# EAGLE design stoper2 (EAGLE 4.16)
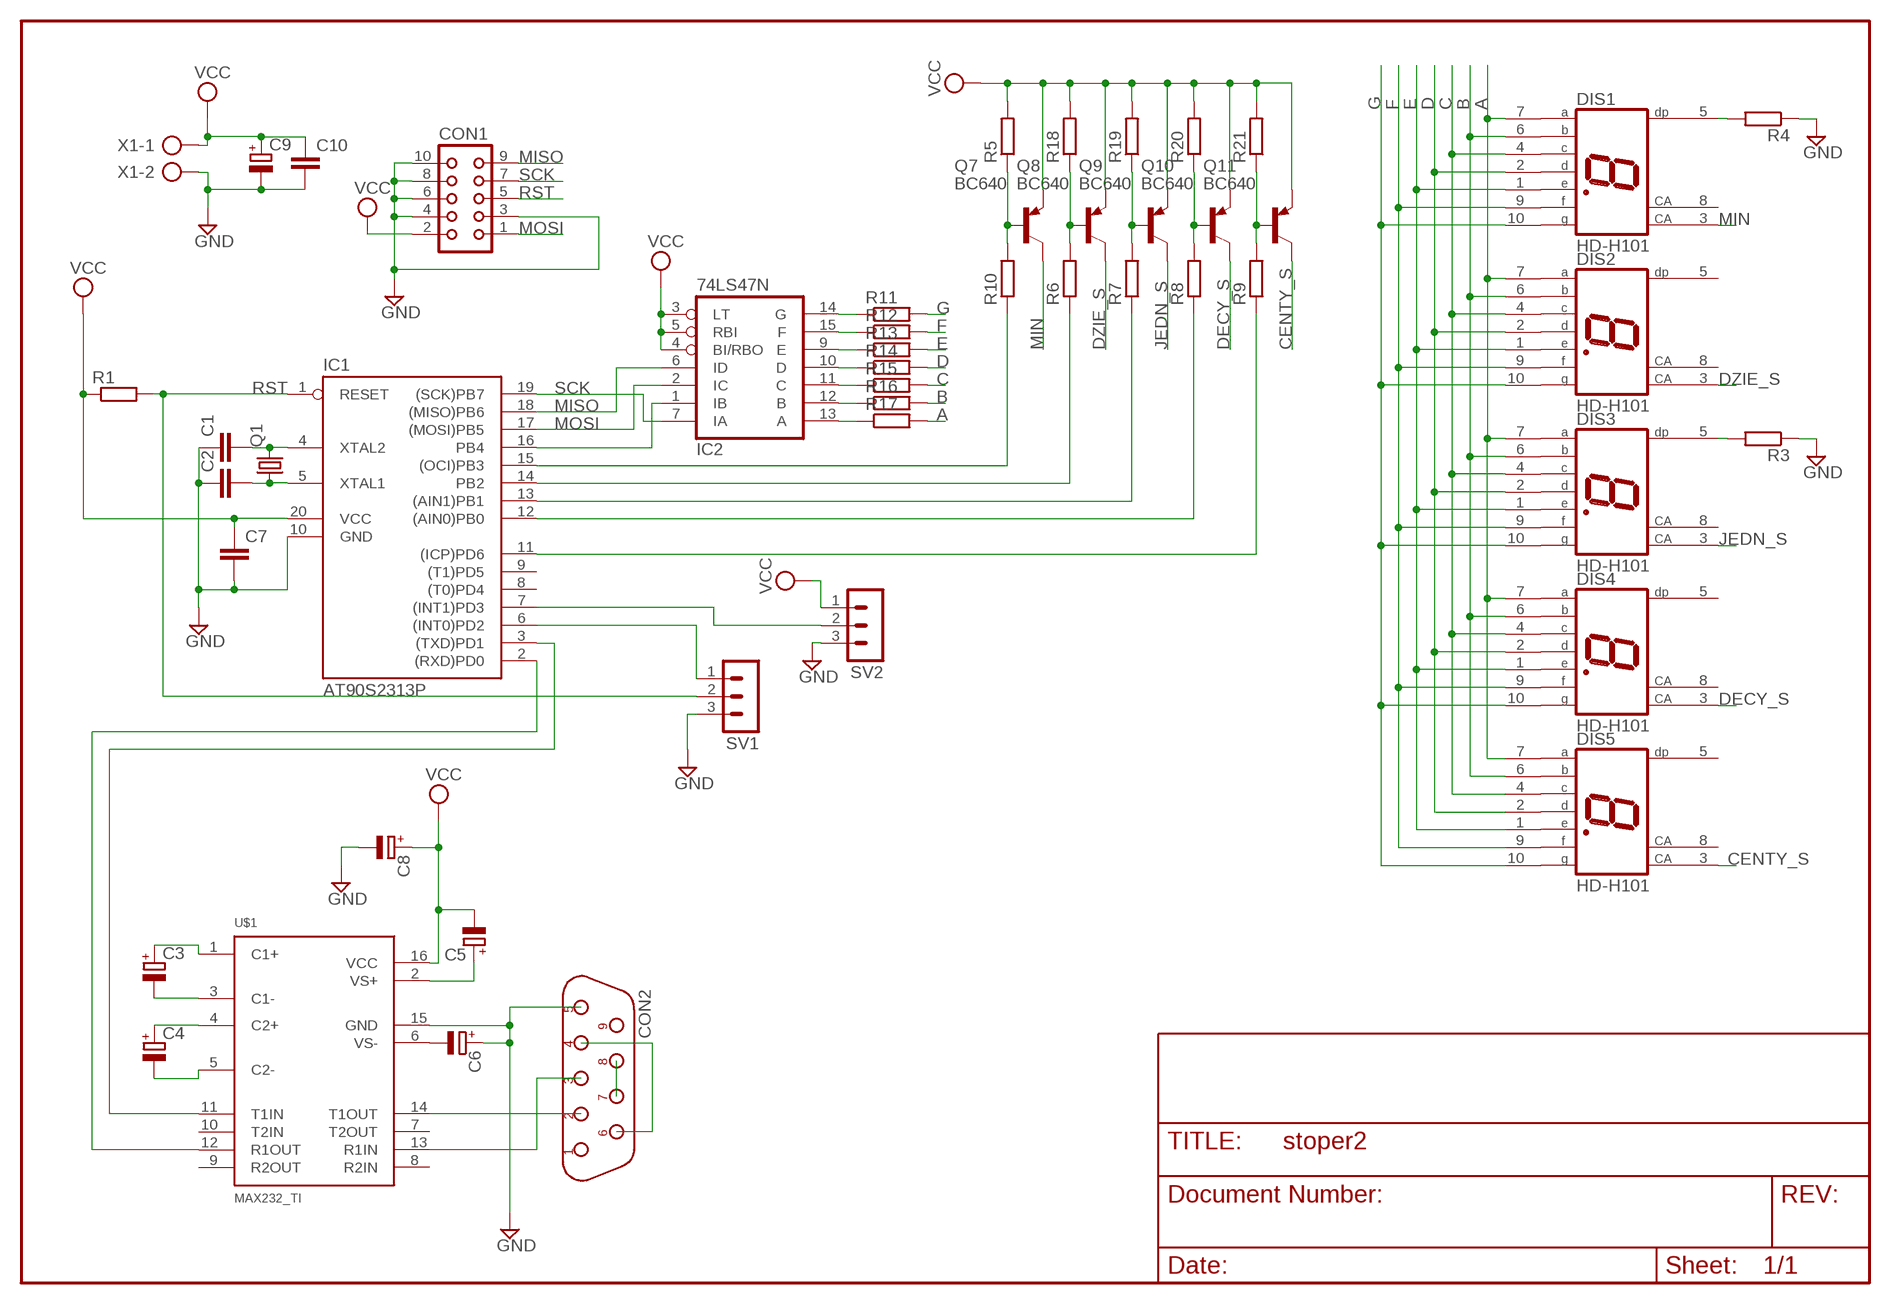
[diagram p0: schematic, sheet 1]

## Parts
C1  C5/2.5  [C5B2.5]
C2  C5/2.5  [C5B2.5]
C3  CPOL-EUE2.5-5  [E2,5-5]
C4  CPOL-EUE2.5-5  [E2,5-5]
C5  CPOL-EUE2.5-5  [E2,5-5]
C6  CPOL-EUE2.5-5  [E2,5-5]
C7  C5/2.5  [C5B2.5]
C8  CPOL-EUE2.5-5  [E2,5-5]
C9  CPOL-EUE2.5-5  [E2,5-5]
C10  C5/2.5  [C5B2.5]
CON1  CON10  [CON10]
CON2  DB9F/90  [D-09F/90]
DIS1  HD-H101  [HDSP-M]
DIS2  HD-H101  [HDSP-M]
DIS3  HD-H101  [HDSP-M]
DIS4  HD-H101  [HDSP-M]
DIS5  HD-H101  [HDSP-M]
IC1  AT90S2313P  [DIL20]
IC2  74LS47N  [DIL16]
Q1  CRYSTALHC49S  [HC49/S]
Q7  BC640  [TO92-BCE]
Q8  BC640  [TO92-BCE]
Q9  BC640  [TO92-BCE]
Q10  BC640  [TO92-BCE]
Q11  BC640  [TO92-BCE]
R1  R-EU_0204/7  [0204/7]
R3  R-EU_0204/5  [0204/5]
R4  R-EU_0204/5  [0204/5]
R5  R-EU_0204/5  [0204/5]
R6  R-EU_0204/5  [0204/5]
R7  R-EU_0204/5  [0204/5]
R8  R-EU_0204/5  [0204/5]
R9  R-EU_0204/5  [0204/5]
R10  R-EU_0204/5  [0204/5]
R11  R-EU_0204/7  [0204/7]
R12  R-EU_0204/7  [0204/7]
R13  R-EU_0204/7  [0204/7]
R14  R-EU_0204/7  [0204/7]
R15  R-EU_0204/7  [0204/7]
R16  R-EU_0204/7  [0204/7]
R17  R-EU_0204/7  [0204/7]
R18  R-EU_0204/5  [0204/5]
R19  R-EU_0204/5  [0204/5]
R20  R-EU_0204/5  [0204/5]
R21  R-EU_0204/5  [0204/5]
SV1  MA03-1  [MA03-1]
SV2  MA03-1  [MA03-1]
U$1  MAX232_TI  [DIL16]
X1  AK500/2  [AK500/2]

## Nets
A: DIS1.7(A) DIS2.7(A) DIS3.7(A) DIS4.7(A) DIS5.7(A) R17.2
B: DIS1.6(B) DIS2.6(B) DIS3.6(B) DIS4.6(B) DIS5.6(B) R16.2
C: DIS1.4(C) DIS2.4(C) DIS3.4(C) DIS4.4(C) DIS5.4(C) R15.2
CENTY_S: DIS5.3(CA) Q11.C
D: DIS1.2(D) DIS2.2(D) DIS3.2(D) DIS4.2(D) DIS5.2(D) R14.2
DECY_S: DIS4.3(CA) Q10.C
DZIE_S: DIS2.3(CA) Q8.C
E: DIS1.1(E) DIS2.1(E) DIS3.1(E) DIS4.1(E) DIS5.1(E) R13.2
F: DIS1.9(F) DIS2.9(F) DIS3.9(F) DIS4.9(F) DIS5.9(F) R12.2
G: DIS1.10(G) DIS2.10(G) DIS3.10(G) DIS4.10(G) DIS5.10(G) R11.2
GND: C1.1 C2.1 C6.+ C7.2 C8.- C9.- C10.2 CON1.3 CON1.4 CON1.6 CON1.8 CON1.10 CON2.5 IC1.10(GND) R3.1 R4.1 SV1.3 SV2.3 U$1.15(GND) X1.2
JEDN_S: DIS3.3(CA) Q9.C
MIN: DIS1.3(CA) Q7.C
MISO: CON1.9 IC1.18((MISO)PB6) IC2.6(ID)
MOSI: CON1.1 IC1.17((MOSI)PB5) IC2.2(IC)
N$1: C2.2 IC1.5(XTAL1) Q1.1
N$2: C1.2 IC1.4(XTAL2) Q1.2
N$3: DIS1.5(DP) R4.2
N$4: DIS3.5(DP) R3.2
N$5: C3.- U$1.3(C1-)
N$6: C3.+ U$1.1(C1+)
N$7: C4.+ U$1.4(C2+)
N$8: C4.- U$1.5(C2-)
N$9: C5.+ U$1.2(VS+)
N$10: C6.- U$1.6(VS-)
N$11: CON2.2 U$1.14(T1OUT)
N$12: CON2.3 U$1.13(R1IN)
N$13: CON2.7 CON2.8
N$14: CON2.4 CON2.6
N$15: IC1.3((TXD)PD1) U$1.11(T1IN)
N$16: IC1.2((RXD)PD0) U$1.12(R1OUT)
N$17: IC1.11((ICP)PD6) R9.1
N$18: Q7.B R5.1 R10.2
N$19: IC1.15((OCI)PB3) R10.1
N$20: IC1.7((INT1)PD3) SV2.2
N$21: Q8.B R6.2 R18.1
N$22: Q9.B R7.2 R19.1
N$23: Q10.B R8.2 R20.1
N$24: Q11.B R9.2 R21.1
N$25: IC1.6((INT0)PD2) SV1.1
N$31: IC2.14(G) R11.1
N$32: IC2.15(F) R12.1
N$33: IC2.9(E) R13.1
N$34: IC2.10(D) R14.1
N$35: IC2.11(C) R15.1
N$36: IC2.12(B) R16.1
N$37: IC2.13(A) R17.1
N$38: IC1.16(PB4) IC2.1(IB)
N$39: IC1.14(PB2) R6.1
N$40: IC1.13((AIN1)PB1) R7.1
N$41: IC1.12((AIN0)PB0) R8.1
RST: CON1.5 IC1.1(RESET) R1.2 SV1.2
SCK: CON1.7 IC1.19((SCK)PB7) IC2.7(IA)
VCC: C5.- C7.1 C8.+ C9.+ C10.1 CON1.2 IC1.20(VCC) IC2.3(LT) IC2.4(BI/RBO) IC2.5(RBI) Q7.E Q8.E Q9.E Q10.E Q11.E R1.1 R5.2 R18.2 R19.2 R20.2 R21.2 SV2.1 U$1.16(VCC) X1.1
Unconnected: CON2.1 CON2.9 DIS1.8(CA) DIS2.5(DP) DIS2.8(CA) DIS3.8(CA) DIS4.5(DP) DIS4.8(CA) DIS5.5(DP) DIS5.8(CA) IC1.8((T0)PD4) IC1.9((T1)PD5) U$1.7(T2OUT) U$1.8(R2IN) U$1.9(R2OUT) U$1.10(T2IN)

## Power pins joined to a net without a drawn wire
GND: IC2.8(GND)
VCC: IC2.16(VCC)

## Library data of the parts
C1 C2 C7 C10 = capacitor-wima:C: CAPACITOR
C3-C6 C8 C9 = rcl:CPOL-EU: POLARIZED CAPACITOR, European symbol
CON1 = con-harting:CON10: CONNECTOR
CON2 = connect:DB9F/90
DIS1-DIS5 = display-hp:HD-H101: LED DISPLAY 1-character 7 segment, decimal point right
IC1 = atmel:AT90S2313: MICROCONTROLLER 2 Kbytes FLASH 128 bytes SRAM 128 bytes EEPROM UART
IC2 = 74xx-eu:74*47: BCD to seven segment DECODER/DRIVER Source: http://www.ee.washington.edu/stores/DataSheets/74ls/74ls47.pdf
Q1 = crystal:CRYSTAL: CRYSTAL
Q7-Q11 = transistor-pnp:BC640*: PNP Transistror
R1 R3-R21 = rcl:R-EU_: RESISTOR, European symbol
SV1 SV2 = con-lstb:MA03-1: PIN HEADER
U$1 = max232ti:MAX232_TI: MAX232, Texas Instruments Version
X1 = con-ptr500:AK500/2: CONNECTOR

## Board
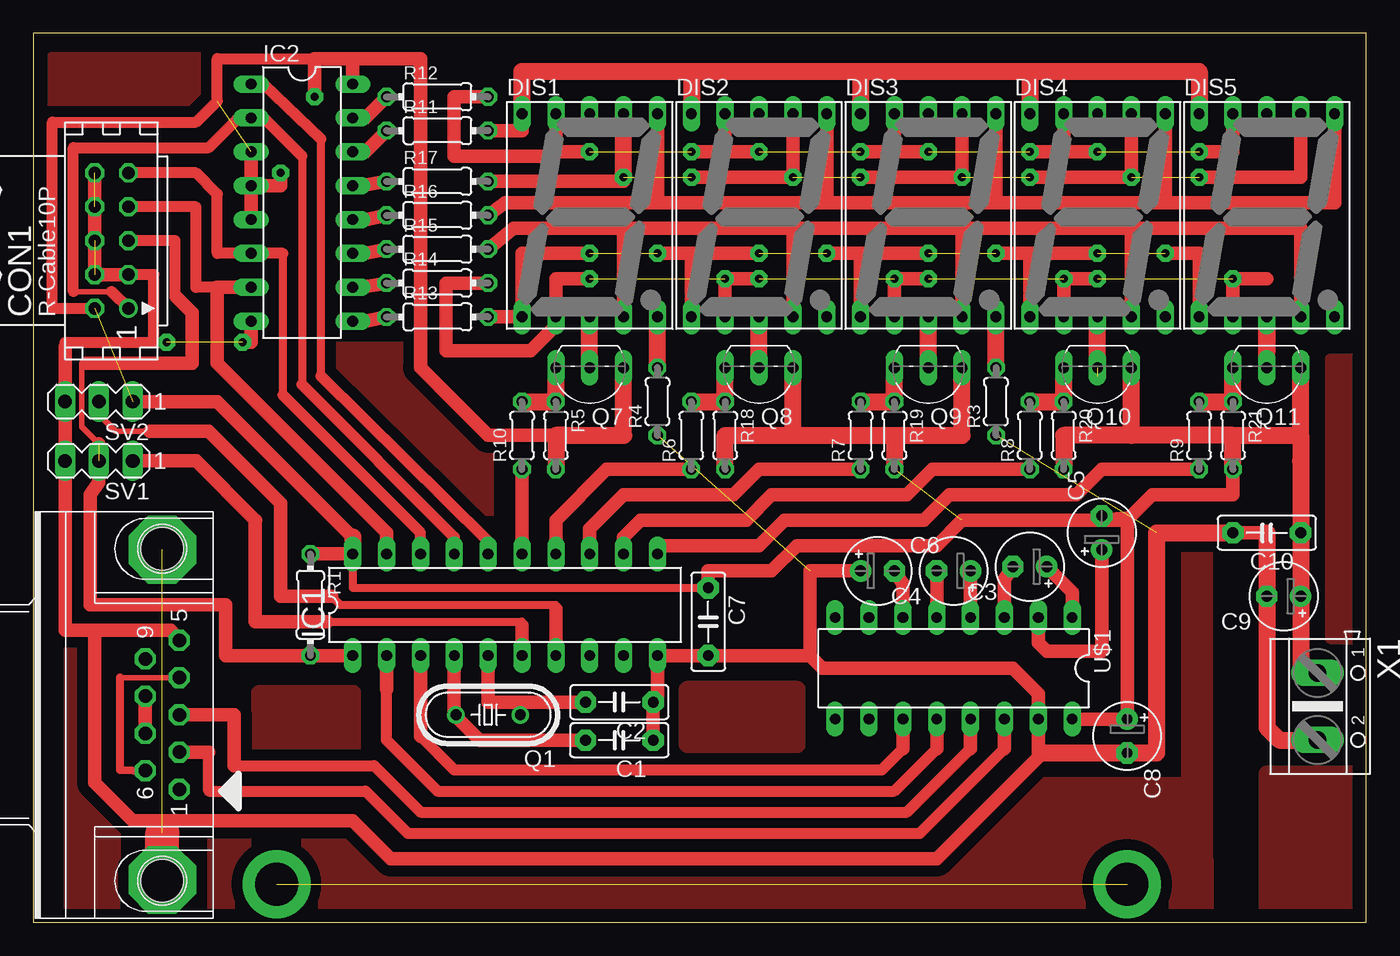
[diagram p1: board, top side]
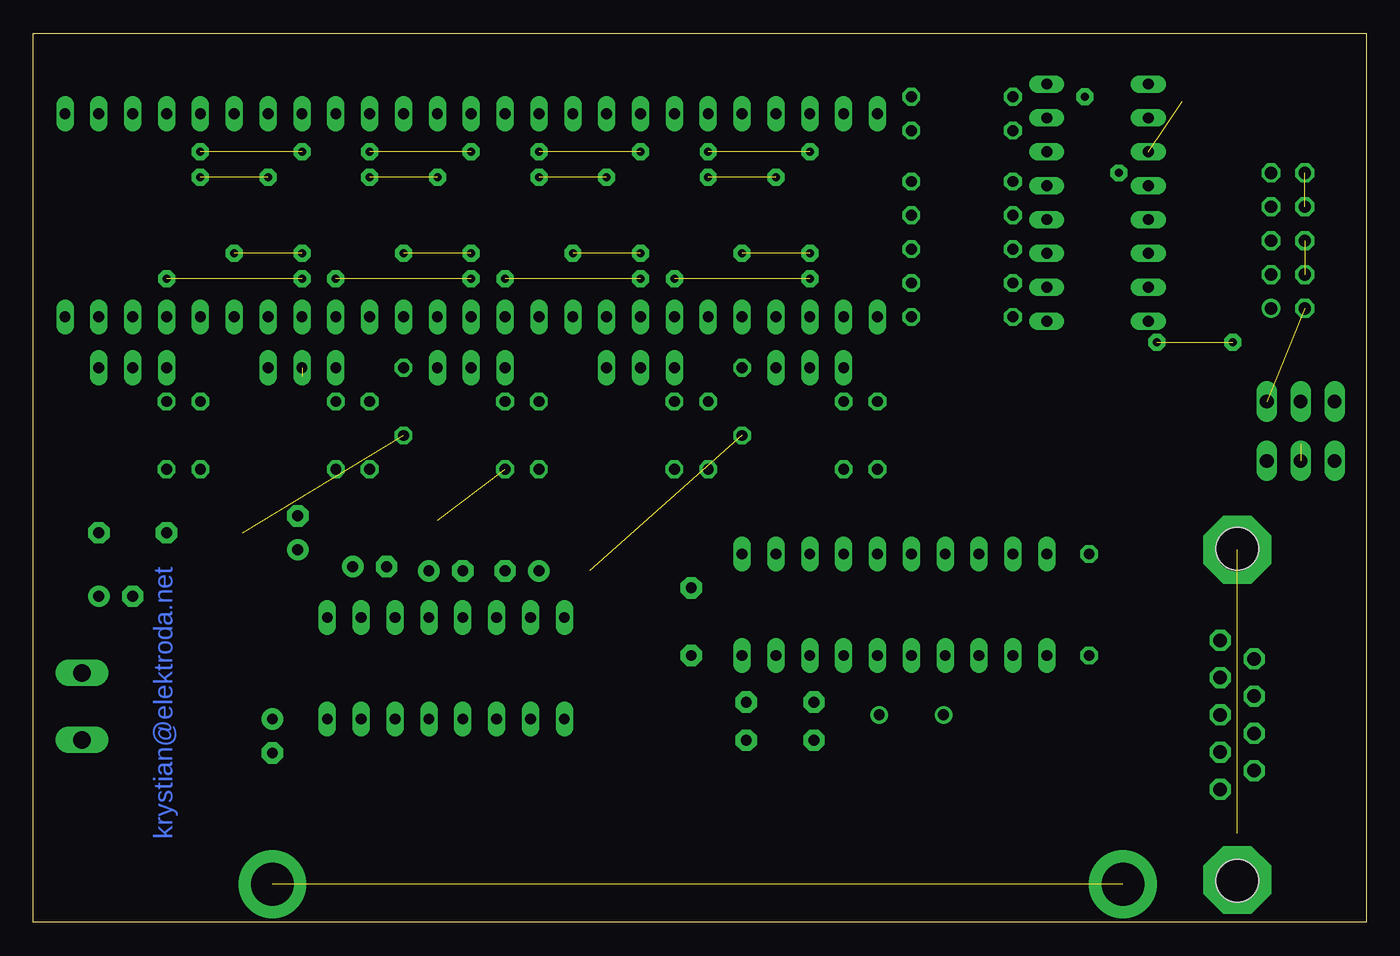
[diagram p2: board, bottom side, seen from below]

Size 100 x 66.67 mm. Coordinates in mm from the lower left corner, seen from the top.
Outline: 0,0 100,0 100,66.67 0,66.67 0,0
Copper layers (1*16): Top 0.035mm / dielectric 1.5mm / Bottom 0.035mm
Design rules "default": minimum track width 10mil, minimum drill 24mil, track to track 8mil, track to pad 8mil, pad to pad 8mil, via to via 8mil, smd to smd 8mil, copper to edge 40mil, drill to drill 8mil, minimum pad ring 10mil, minimum via ring 8mil, stop-mask expansion 4mil, vias tented up to drill 0mil, thermal gap 10mil

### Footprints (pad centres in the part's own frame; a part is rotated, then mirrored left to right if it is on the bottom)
C5B2.5 = drill 0.813 pad 1.6 octagon: 1 -2.54,0; 2 2.54,0
E2,5-5 = drill 0.813 pad 1.6 round: + -1.27,0 | drill 0.813 pad 1.6 octagon: - 1.27,0
CON10 = drill 0.914 round: 1 -5.08,-1.27 | drill 0.914 octagon: 2 -5.08,1.27; 3 -2.54,-1.27; 4 -2.54,1.27; 5 0,-1.27; 6 0,1.27; 7 2.54,-1.27; 8 2.54,1.27; 9 5.08,-1.27; 10 5.08,1.27
D-09F/90 = drill 1.016 pad 1.575 octagon: 1 -5.588,-1.27; 2 -2.794,-1.27; 3 0,-1.27; 4 2.794,-1.27; 5 5.588,-1.27; 6 -4.191,1.27; 7 -1.397,1.27; 8 1.397,1.27; 9 4.191,1.27 | hole 3.2: 12.446,0; -12.446,0
HDSP-M = drill 0.813 long: 1 -5.08,-7.62; 2 -2.54,-7.62; 3 0,-7.62; 4 2.54,-7.62; 5 5.08,-7.62; 6 5.08,7.62; 7 2.54,7.62; 8 0,7.62; 9 -2.54,7.62; 10 -5.08,7.62
DIL20 = drill 0.813 long: 1 -11.43,-3.81; 2 -8.89,-3.81; 3 -6.35,-3.81; 4 -3.81,-3.81; 5 -1.27,-3.81; 6 1.27,-3.81; 7 3.81,-3.81; 8 6.35,-3.81; 9 8.89,-3.81; 10 11.43,-3.81; 11 11.43,3.81; 12 8.89,3.81; 13 6.35,3.81; 14 3.81,3.81; 15 1.27,3.81; 16 -1.27,3.81; 17 -3.81,3.81; 18 -6.35,3.81; 19 -8.89,3.81; 20 -11.43,3.81
DIL16 = drill 0.813 long: 1 -8.89,-3.81; 2 -6.35,-3.81; 3 -3.81,-3.81; 4 -1.27,-3.81; 5 1.27,-3.81; 6 3.81,-3.81; 7 6.35,-3.81; 8 8.89,-3.81; 9 8.89,3.81; 10 6.35,3.81; 11 3.81,3.81; 12 1.27,3.81; 13 -1.27,3.81; 14 -3.81,3.81; 15 -6.35,3.81; 16 -8.89,3.81
HC49/S = drill 0.813 round: 1 -2.413,0; 2 2.413,0
TO92-BCE = drill 0.813 long: B 2.54,0; C 0,0; E -2.54,0
0204/7 = drill 0.813 octagon: 1 -3.81,0; 2 3.81,0
0204/5 = drill 0.813 octagon: 1 -2.54,0; 2 2.54,0
MA03-1 = drill 1.016 long: 1 -2.54,0; 2 0,0; 3 2.54,0
AK500/2 = drill 1.321 long: 1 -2.515,0; 2 2.515,0

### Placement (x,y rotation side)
C1  43.97,13.65 180 top
C2  43.97,16.51 180 top
C3  74.77,26.66 180 top
C4  69.05,26.35 180 top
C5  80.16,29.2 90 top
C6  63.34,26.35 0 top
C7  50.63,22.54 270 top
C8  82.07,13.97 270 top
C9  93.81,24.44 180 top
C10  92.55,29.2 180 top
CON1  5.87,51.11 90 top
CON2  9.68,15.55 90 top
DIS1  41.74,53.02 0 top
DIS2  54.45,53.02 0 top
DIS3  67.14,53.02 0 top
DIS4  79.84,53.02 0 top
DIS5  92.55,53.02 0 top
IC1  35.39,23.81 0 top
IC2  20.15,53.97 270 top
Q1  34.12,15.55 180 top
Q7  41.74,41.59 180 top
Q8  54.45,41.59 180 top
Q9  67.14,41.59 180 top
Q10  79.84,41.59 180 top
Q11  92.55,41.59 180 top
R1  20.79,23.81 270 top
R3  72.22,39.05 90 top
R4  46.82,39.05 90 top
R5  39.2,36.51 270 top
R6  49.37,36.51 90 top
R7  62.06,36.51 90 top
R8  74.77,36.51 90 top
R9  87.47,36.51 90 top
R10  36.66,36.51 90 top
R11  30.31,59.37 0 top
R12  30.31,61.91 0 top
R13  30.31,45.4 0 top
R14  30.31,47.94 0 top
R15  30.31,50.48 0 top
R16  30.31,53.02 0 top
R17  30.31,55.56 0 top
R18  51.91,36.51 270 top
R19  64.61,36.51 270 top
R20  77.3,36.51 270 top
R21  90,36.51 270 top
SV1  4.92,34.6 180 top
SV2  4.92,39.05 180 top
U$1  69.05,19.05 180 top
X1  96.36,16.19 270 top

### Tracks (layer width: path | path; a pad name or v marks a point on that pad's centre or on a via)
A  (via drill 0.6 pad 1.27)  (4 unrouted)
  Top 1.016: DIS4.7 v82.39,55.88 v74.77,55.88 | DIS3.7 v69.69,55.88 v62.06,55.88 | DIS2.7 v56.98,55.88 v49.37,55.88 | DIS5.7 95.08,55.88 v87.47,55.88 | v44.28,55.88 44.28,55.56 R17.2
  Top 1.27: v44.28,55.88 DIS1.7
B
  Top 1.016: 46.82,53.97 DIS1.6 | 46.82,53.97 59.52,53.97 | 59.52,53.97 DIS2.6 | 72.22,53.97 DIS3.6 | 59.52,53.97 72.22,53.97 | 84.92,53.97 DIS4.6 | 72.22,53.97 84.92,53.97 | DIS5.6 97.62,53.97 84.92,53.97 | 46.82,53.97 35.39,53.97 R16.2
C
  Top 1.016: DIS5.4 95.08,52.06 82.39,52.06 | 82.39,52.06 DIS4.4 | 44.28,52.06 DIS1.4 | 44.28,52.06 56.98,52.06 | 56.98,52.06 DIS2.4 | 69.69,52.06 82.39,52.06 | 69.69,52.06 DIS3.4 | 56.98,52.06 69.69,52.06 | 44.28,52.06 36.03,52.06 R15.2
CENTY_S
  Top 1.27: 92.55,42.86 DIS5.3 Q11.C
D  (via drill 0.6 pad 1.27)  (4 unrouted)
  Top 1.016: DIS5.2 v90,48.26 92.55,48.26 | DIS4.2 v77.3,48.26 v79.84,48.26 | DIS3.2 v64.61,48.26 v67.14,48.26 | DIS2.2 v51.91,48.26 v54.45,48.26 | v41.74,48.26 39.2,48.26 DIS1.2 39.2,44.76 37.3,42.86 30.95,42.86 30.95,47.94 R14.2
DECY_S  (1 unrouted)
  Top 1.27: 79.84,40.95 DIS4.3 79.84,46.03
DZIE_S
  Top 1.27: Q8.C DIS2.3
E  (via drill 0.6 pad 1.27)  (4 unrouted)
  Top 1.016: DIS5.1 87.47,50.16 v84.92,50.16 | DIS3.1 62.06,50.16 | DIS2.1 49.37,50.16 | 74.77,50.16 v79.84,50.16 | DIS4.1 74.77,50.16 | 74.77,50.16 v72.22,50.16 | 62.06,50.16 v67.14,50.16 | 62.06,50.16 v59.52,50.16 | 49.37,50.16 v54.45,50.16 | 49.37,50.16 v46.82,50.16 | v41.74,50.16 36.66,50.16 DIS1.1 R13.2
F  (via drill 0.6 pad 1.27)  (4 unrouted)
  Top 1.016: 51.91,57.78 DIS2.9 | 64.61,57.78 DIS3.9 | 77.3,57.78 DIS4.9 | DIS5.9 90,57.78 v87.47,57.78 | 39.2,58.1 39.2,57.78 v41.74,57.78 | 39.2,58.1 DIS1.9 | v49.37,57.78 51.91,57.78 | 51.91,57.78 v54.45,57.78 | v62.06,57.78 64.61,57.78 | 64.61,57.78 v67.14,57.78 | v74.77,57.78 77.3,57.78 | 77.3,57.78 v79.84,57.78 | 39.2,58.1 38.57,57.46 31.58,57.46 31.58,61.91 R12.2
G
  Top 1.016: R11.2 36.66,59.37 DIS1.10
  Top 1.27: DIS1.10 36.66,63.81 49.37,63.81 | 49.37,63.81 DIS2.10 | 49.37,63.81 62.06,63.81 | 62.06,63.81 DIS3.10 | 62.06,63.81 74.77,63.81 | 74.77,63.81 DIS4.10 | 74.77,63.81 87.47,63.81 DIS5.10
GND  (via drill 0.6 pad 1.27)  (5 unrouted)
  Top 0.813: 49.37,20 49.42,19.95 | CON1.3 9.04,48.57 9.04,43.49 | 2.39,43.18 2.39,43.48 2.38,43.49 9.04,43.49 | 9.04,43.49 v10,43.49
  Top 1.016: 90.32,29.2 C10.2 92.55,29.2 | C6.+ 58.25,26.35 58.25,20 | 58.25,20 C7.2 49.37,20 IC1.10 46.82,16.82 C2.1 C1.1 | 75.4,12.38 75.4,14.92 | CON2.5 10.31,21.9 4.6,21.9 | 4.6,21.9 4.6,10.47 7.46,7.62 9.68,7.62 | 9.68,7.62 23.96,7.62 26.82,4.76 67.78,4.76 75.4,12.38 | 75.4,14.92 U$1.15 | 75.4,14.92 75.4,17.14 73.5,19.05 59.21,19.05 58.25,20 | CON1.4 CON1.3 CON1.4 | CON1.4 CON1.10 | IC2.8 16.34,43.49 v15.71,43.49 | 2.39,43.18 2.38,43.18 SV2.3 | 75.4,12.38 75.72,12.69 | SV1.3 2.38,34.92 | 4.6,21.9 2.38,21.9 SV1.3 | SV2.3 2.38,39.37 | SV1.3 SV2.3 | 9.68,5.39 9.68,7.62
  Top 1.27: 75.72,12.69 C8.- 84.29,12.69 84.29,29.2 C10.2 | 92.55,24.12 92.55,14.6 93.5,13.65 96.36,13.65 X1.2 | 92.55,24.12 C9.- 92.55,29.2 92.55,24.12
JEDN_S
  Top 1.27: Q9.C DIS3.3
MIN
  Top 1.27: Q7.C DIS1.3
MISO
  Top 0.61: 18.73,39.52 18.73,50.16
  Top 0.813: IC1.18 29.04,29.2 18.73,39.52 | 18.73,50.16 IC2.6 13.81,50.16 13.81,54.61 12.22,56.19 CON1.9
MOSI
  Top 0.406: 3.01,47.3 5.87,47.3
  Top 0.61: 20.15,57.46 20.15,40.32
  Top 0.813: IC1.17 31.58,28.89 20.15,40.32 | 20.15,57.46 17.3,60.32 IC2.2 15.39,60.32 13.17,58.1 3.01,58.1 3.01,47.3 | 5.87,47.3 CON1.1
N$1
  Top 1.016: 36.54,16.51 C2.2 | IC1.5 34.12,16.51 36.54,16.51 | 36.54,16.51 Q1.1
N$2
  Top 1.016: 31.58,15.55 IC1.4 | Q1.2 31.58,15.55 | C1.2 33.49,13.65 31.58,15.55
N$3
  Top 1.27: R4.2 DIS1.5
N$4
  Top 1.27: R3.2 DIS3.5
N$5
  Top 1.016: U$1.3 72.86,25.71 C3.-
N$6
  Top 1.016: U$1.1 77.94,24.76 C3.+
N$7
  Top 1.016: U$1.4 C4.+
N$8
  Top 1.016: U$1.5 C4.-
N$9
  Top 1.016: U$1.2 75.4,20.95 76.03,20.32 80.16,20.32 C5.+
N$10
  Top 1.016: 65.24,22.54 U$1.6 65.24,25.4 C6.-
N$11
  Top 0.813: 13.17,12.76 13.17,9.84 24.92,9.84 28.09,6.66 66.51,6.66 72.86,13.01
  Top 1.016: 13.17,12.76 CON2.2 | 72.86,13.01 U$1.14
N$12
  Top 0.813: 15.08,11.74 25.55,11.74 29.04,8.25 65.56,8.25 70.32,13.01
  Top 1.016: CON2.3 15.08,15.55 15.08,11.74 | 70.32,13.01 U$1.13
N$13
  Top 1.016: CON2.7 CON2.8
N$14
  Top 0.406: 6.5,18.35 CON2.4
  Top 0.61: CON2.6 6.5,11.42 6.5,18.35
N$15
  Top 0.813: 29.04,13.97 31.58,11.42 63.65,11.42 65.24,13.01
  Top 1.016: 29.04,13.97 IC1.3 | 65.24,13.01 U$1.11
N$16
  Top 0.813: 26.5,17.46 26.5,13.65 30.31,9.84 64.61,9.84 67.78,13.01
  Top 1.016: 26.5,17.46 IC1.2 | 67.78,13.01 U$1.12
N$17
  Top 1.016: IC1.11 46.82,28.25 54.45,28.25 56.35,30.16 66.83,30.16 68.73,32.06 78.26,32.06 80.16,33.97 R9.1
N$18
  Top 1.27: R10.2 R5.1 Q7.B
N$19
  Top 1.016: IC1.15 R10.1
N$20
  Top 0.406: 4.92,38.09 6.18,36.83 8.73,36.83
  Top 0.61: 39.2,23.49 39.2,23.81 23.01,23.81 22.38,24.44
  Top 1.016: 39.2,23.49 IC1.7 | 22.38,24.44 18.57,24.44 18.57,31.43 13.17,36.83 8.73,36.83 | SV2.2 4.92,38.09
N$21
  Top 1.27: R6.2 R18.1 Q8.B
N$22
  Top 1.27: R7.2 R19.1 Q9.B
N$23
  Top 1.27: Q10.B R20.1 R8.2
N$24
  Top 1.27: Q11.B R21.1 R9.2
N$25
  Top 0.61: 22.06,22.54 36.66,22.54 36.66,22.22
  Top 1.016: 36.66,22.22 IC1.6 | SV1.1 12.22,34.6 16.66,30.16 16.66,22.54 22.06,22.54
N$26  (via drill 0.6 pad 1.27)
  other vias: 18.57,56.19
N$27  (via drill 3.2 pad 5.08)  (1 unrouted)
  Top 2.54: v9.68,3.17 9.68,6.66
  other vias: 9.68,27.94
N$28  (via drill 3.2 pad 5.08)  (1 unrouted)
  other vias: 18.25,2.85 82.07,2.85
N$29
  pour Top (isolate 0.813, rank 2): 1.42,59.69 1.42,64.77 13.81,64.77 13.81,60 1.42,60
N$30
  pour Top (isolate 0.813, rank 2): 49.05,17.46 49.05,13.33 57.3,13.33 57.3,17.46
N$31
  Top 1.016: R11.1 24.92,57.78 IC2.14
N$32
  Top 1.016: R12.1 24.92,60.32 IC2.15
N$33
  Top 1.016: IC2.9 24.92,45.08 R13.1
N$34
  Top 1.016: IC2.10 24.6,47.62 R14.1
N$35
  Top 1.016: IC2.11 24.92,50.16 R15.1
N$36
  Top 1.016: IC2.12 24.92,52.7 R16.1
N$37
  Top 1.016: IC2.13 24.6,55.24 R17.1
N$38
  Top 0.61: 21.58,40.95 21.58,58.73
  Top 0.813: IC1.16 34.12,28.57 21.58,40.95 | 21.58,58.73 17.3,62.86 IC2.1
N$39
  Top 1.016: R6.1 43.02,33.97 39.2,30.16 IC1.14
N$40
  Top 1.016: R7.1 54.45,33.97 52.54,32.06 44.28,32.06 41.74,29.52 IC1.13
N$41
  Top 1.016: R8.1 67.46,33.97 65.56,32.06 55.4,32.06 53.49,30.16 45.55,30.16 44.28,28.89 IC1.12
N$42
  pour Top (isolate 0.813, rank 2): 21.74,43.18 29.04,43.18 29.04,41.59 34.12,36.51 34.12,28.25 34.12,28.57 22.06,40.95
N$43
  pour Top (isolate 0.813, rank 2): 67.78,4.76 88.1,4.76 88.1,28.89 86.51,28.89 86.51,10.47 74.77,10.47 69.05,4.76
N$44
  pour Top (isolate 0.813, rank 2): 92.55,11.11 92.55,0.95 98.89,0.95 98.89,11.11
N$45
  pour Top (isolate 0.813, rank 2): 23.96,17.14 16.98,17.14 16.98,12.06 23.96,12.06
N$46
  pour Top (isolate 0.813, rank 2): 13.49,7.62 23.96,7.62 26.82,4.76 88.1,4.76 88.1,0.31 13.49,0.31
N$47
  pour Top (isolate 0.813, rank 2): 2.69,21.9 2.69,0.31 6.18,0.31 6.18,8.88 4.6,10.47 4.6,21.9 3.01,21.9 2.69,21.59 2.69,21.27
N$48
  pour Top (isolate 0.813, rank 2): 97.31,42.22 97.31,21.27 99.53,21.27 99.53,42.22
RST  (1 unrouted)
  Top 0.406: 4.92,35.87 3.64,37.14 3.64,41.91 3.96,41.91
  Top 0.813: CON1.5 10.63,51.11 10.63,46.87 10.74,46.87
  Top 1.016: IC1.1 R1.2 14.44,20 14.44,23.81 4.28,23.81 4.28,32.06 4.92,33.02 4.92,35.87 | 3.96,41.91 11.9,41.91 11.9,45.72 10.74,46.87
SCK
  Top 0.813: CON1.7 12.22,53.65 12.22,47.62 13.81,47.62
  Top 1.016: IC1.19 26.5,29.2 13.81,41.91 13.81,47.62 IC2.7
VCC  (via drill 0.6 pad 1.27)  (3 unrouted)
  Top 0.61: IC1.20 23.96,25.08 C7.1
  Top 0.813: CON1.2 1.42,46.03 1.42,60 12.22,60 13.81,61.59 13.81,64.77 21.11,64.77
  Top 1.016: 23.96,64.77 29.04,64.77 29.04,41.59 34.12,36.51 39.84,36.51 | 23.96,64.77 IC2.16 | IC2.5 IC2.4 | IC2.4 IC2.3 IC2.4 | C7.1 50.63,26.35 55.4,26.35 57.3,28.25 67.78,28.25 69.69,30.16 79.69,30.16 | 82.23,30.32 81.43,30.16 | 82.23,30.32 83.97,32.06 85.88,32.06 | 85.88,32.06 87.47,32.06 | R21.2 90,32.06 85.88,32.06 | 79.69,30.16 82.23,30.32 | 79.69,30.16 C5.- | 79.69,30.16 81.43,30.16 | 81.43,30.16 82.07,30.16 C8.+ U$1.16 | IC1.20 R1.1 | SV2.1 13.81,39.05 23.96,28.89 | 23.96,64.77 21.11,64.77 v21.11,61.91 | IC2.4 18.57,55.24 18.57,56.19
  Top 1.27: 95.08,36.51 Q11.E | 56.98,36.51 51.91,36.51 R18.2 | 56.98,36.51 64.61,36.51 | 64.61,36.51 69.69,36.51 Q9.E | 82.39,36.51 77.3,36.51 R20.2 | 90,36.51 82.39,36.51 | 90,36.51 95.08,36.51 | R21.2 90,36.51 | 82.39,36.51 Q10.E | 64.61,36.51 R19.2 | 56.98,36.51 Q8.E | Q7.E 44.28,36.51 39.84,36.51 39.2,36.51 R5.2 | 95.08,36.51 95.08,34.6 | C10.1 C9.+ | C9.+ 95.08,18.73 96.36,18.73 X1.1 | 95.08,36.51 C10.1 | C10.1 C9.+ | 23.96,28.89 IC1.20

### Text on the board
Bottom: krystian@elektroda.net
